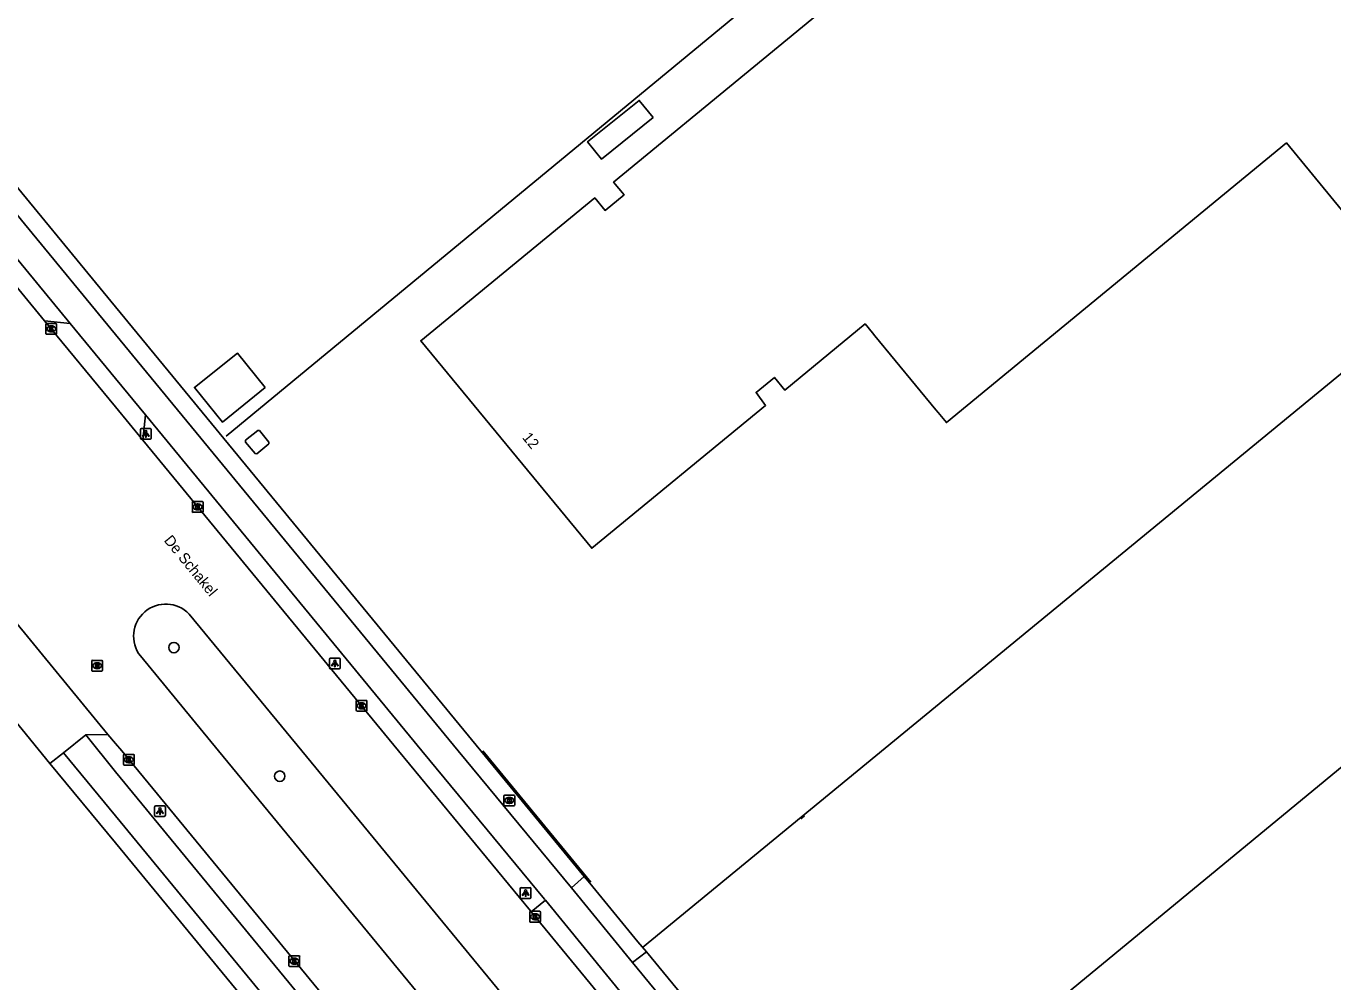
# Model space of a CAD drawing. Extents: x 156141 to 158132, y 385651 to 388399.
# Drawn here: x 156991.7 to 157113.6, y 386478.5 to 386567.6 of the extents above; entities that cross this region are included whole.
import ezdxf

# ---------------------------------------------------------------- set-up
doc = ezdxf.new("R2010")
doc.units = 0
for name, color, linetype in [('IMGEO_Boom', 7, 'Continuous'), ('IMGEO_Brandkraan', 7, 'Continuous'), ('IMGEO_Fietspad_gesloten', 7, 'Continuous'), ('IMGEO_Hek', 7, 'Continuous'), ('IMGEO_Kolk', 7, 'Continuous'), ('IMGEO_Lage_trafo', 7, 'Continuous'), ('IMGEO_Lichtpunt', 7, 'Continuous'), ('IMGEO_Openbare_ruimte_label', 7, 'Continuous'), ('IMGEO_Pand', 7, 'Continuous'), ('IMGEO_Pand_nummerreeks', 7, 'Continuous'), ('IMGEO_Rijbaan_lokaal_gesloten', 7, 'Continuous'), ('IMGEO_Rijbaan_lokaal_open', 7, 'Continuous'), ('IMGEO_Rioolput', 7, 'Continuous'), ('IMGEO_Voetpad_open', 7, 'Continuous')]:
    doc.layers.add(name, color=color, linetype=linetype)

msp = doc.modelspace()

# ---------------------------------------------------------------- linework, layer by layer
at = {"layer": 'IMGEO_Boom'}
for centre in [(157005.46, 386509.64), (157015.33, 386497.65)]:
    msp.add_circle(centre, 0.489, dxfattribs=at)
at = {"layer": 'IMGEO_Brandkraan'}
for p, q in [((157036.25, 386494.96), (157036.25, 386495.81)), ((157036.32, 386495.89), (157037.17, 386495.89)), ((157036.73, 386495.67), (157036.76, 386495.67)), ((157037.25, 386495.81), (157037.25, 386494.96)), ((157037.17, 386494.89), (157036.32, 386494.89)), ((157036.76, 386495.11), (157036.73, 386495.11))]:
    msp.add_line(p, q, dxfattribs=at)
for points in [[(157036.25, 386494.96), (157036.25, 386495.81)], [(157036.32, 386495.89), (157037.17, 386495.89)], [(157036.59, 386495.59), (157036.59, 386495.19), (157036.81, 386495.19)], [(157036.83, 386495.59), (157036.59, 386495.59)], [(157037.25, 386495.81), (157037.25, 386494.96)], [(157037.17, 386494.89), (157036.32, 386494.89)], [(157036.77, 386495.51), (157036.72, 386495.51), (157036.72, 386495.43)], [(157036.72, 386495.43), (157036.77, 386495.43)], [(157036.78, 386495.35), (157036.72, 386495.35), (157036.72, 386495.27)], [(157036.72, 386495.27), (157036.78, 386495.27)]]:
    msp.add_lwpolyline(points, dxfattribs=at)
for centre, radius, start, end in [((157036.32, 386495.81), 0.0765, 91.552, 178.448), ((157036.32, 386495.81), 0.0765, 91.552, 178.448), ((157036.83, 386495.44), 0.145, 59.4692, 91.5367), ((157036.85, 386495.49), 0.0922, 285.5137, 58.1501), ((157037.17, 386495.81), 0.0765, 1.552, 88.448), ((157037.17, 386495.81), 0.0765, 1.552, 88.448), ((157036.32, 386494.96), 0.0765, 181.552, 268.448), ((157036.32, 386494.96), 0.0765, 181.552, 268.448), ((157036.77, 386495.47), 0.0379, 267.8285, 90.9355), ((157036.78, 386495.31), 0.0404, 269.8759, 90.5077), ((157036.81, 386495.44), 0.251, 268.6676, 293.5347), ((157036.86, 386495.3), 0.105, 301.3115, 78.989), ((157037.17, 386494.96), 0.0765, 271.552, 358.448), ((157037.17, 386494.96), 0.0765, 271.552, 358.448)]:
    msp.add_arc(centre, radius, start, end, dxfattribs=at)
for centre, major_axis, ratio, start_param, end_param in [((157036.73, 386495.39), (-0.387, 0.002), 0.722429, 4.712389, 7.853982), ((157036.76, 386495.39), (-0.39, 0.002), 0.717154, 1.570796, 4.712389)]:
    msp.add_ellipse(centre, major_axis=major_axis, ratio=ratio, start_param=start_param, end_param=end_param, dxfattribs=at)
at = {"layer": 'IMGEO_Fietspad_gesloten'}
for points in [[(157042.54, 386487.23), (157031.99, 386500), (157000, 386538.85), (156991.51, 386549.16), (156987.15, 386554.49)], [(156995.78, 386539.85), (156987.04, 386550.47), (156985.5, 386552.36)], [(157002.8, 386531.34), (157028.6, 386500), (157040.04, 386486.18), (157040.11, 386486.1)], [(156997.23, 386501.52), (157000, 386498.06), (157086.19, 386393.38)], [(157084.09, 386391.8), (157000, 386493.95), (156995.15, 386499.84)], [(157048.25, 386480.29), (157042.54, 386487.23)], [(157106.12, 386409.97), (157048.25, 386480.29)]]:
    msp.add_lwpolyline(points, dxfattribs=at)
at = {"layer": 'IMGEO_Hek'}
for points in [[(157112.51, 386613.65), (157010.32, 386529.35)], [(157151.72, 386565.87), (157049.18, 386481.68)], [(157044.35, 386487.76), (157034.27, 386500)], [(157064.27, 386493.95), (157063.94, 386493.68)]]:
    msp.add_lwpolyline(points, dxfattribs=at)
at = {"layer": 'IMGEO_Kolk'}
for p, q in [((156993.52, 386538.93), (156993.52, 386539.78)), ((156993.59, 386539.86), (156994.45, 386539.86)), ((156994.01, 386539.64), (156994.03, 386539.64)), ((156994.52, 386539.78), (156994.52, 386538.93)), ((156994.45, 386538.86), (156993.59, 386538.86)), ((156994.03, 386539.08), (156994, 386539.08)), ((157007.18, 386522.33), (157007.18, 386523.19)), ((157007.25, 386523.26), (157008.1, 386523.26)), ((157007.69, 386522.48), (157007.66, 386522.48)), ((157007.67, 386523.04), (157007.69, 386523.04)), ((157008.18, 386523.19), (157008.18, 386522.33)), ((157008.1, 386522.26), (157007.25, 386522.26)), ((157022.47, 386503.79), (157022.47, 386504.64)), ((157022.54, 386504.71), (157023.39, 386504.71)), ((157022.95, 386504.49), (157022.98, 386504.49)), ((157023.47, 386504.64), (157023.47, 386503.79)), ((157023.39, 386503.71), (157022.54, 386503.71)), ((157022.98, 386503.93), (157022.95, 386503.93)), ((157000.76, 386498.75), (157000.76, 386499.61)), ((157000.83, 386499.68), (157001.69, 386499.68)), ((157001.25, 386499.46), (157001.27, 386499.46)), ((157001.76, 386499.61), (157001.76, 386498.75)), ((157001.69, 386498.68), (157000.83, 386498.68)), ((157001.27, 386498.9), (157001.25, 386498.9)), ((157038.65, 386484.12), (157038.65, 386484.97)), ((157038.73, 386485.05), (157039.58, 386485.05)), ((157039.14, 386484.82), (157039.17, 386484.82)), ((157039.66, 386484.97), (157039.66, 386484.12)), ((157039.58, 386484.04), (157038.73, 386484.04)), ((157039.16, 386484.27), (157039.14, 386484.27)), ((157016.27, 386480.9), (157017.12, 386480.9)), ((157016.19, 386479.97), (157016.19, 386480.83)), ((157017.12, 386479.9), (157016.27, 386479.9)), ((157016.68, 386480.68), (157016.71, 386480.68)), ((157016.7, 386480.12), (157016.68, 386480.12)), ((157017.19, 386480.83), (157017.19, 386479.97))]:
    msp.add_line(p, q, dxfattribs=at)
for points in [[(156993.52, 386538.93), (156993.52, 386539.78)], [(156993.59, 386539.86), (156994.45, 386539.86)], [(156993.84, 386539.56), (156993.96, 386539.56), (156993.96, 386539.41), (156994.09, 386539.56), (156994.26, 386539.56), (156994.11, 386539.41), (156994.26, 386539.16), (156994.11, 386539.16), (156994.03, 386539.32), (156993.96, 386539.25), (156993.96, 386539.16), (156993.84, 386539.16), (156993.84, 386539.56)], [(156994.52, 386539.78), (156994.52, 386538.93)], [(156994.45, 386538.86), (156993.59, 386538.86)], [(157007.18, 386522.33), (157007.18, 386523.19)], [(157007.25, 386523.26), (157008.1, 386523.26)], [(157007.5, 386522.96), (157007.62, 386522.96), (157007.62, 386522.81), (157007.75, 386522.96), (157007.92, 386522.96), (157007.77, 386522.81), (157007.92, 386522.56), (157007.77, 386522.56), (157007.69, 386522.72), (157007.62, 386522.66), (157007.62, 386522.56), (157007.5, 386522.56), (157007.5, 386522.96)], [(157008.18, 386523.19), (157008.18, 386522.33)], [(157008.1, 386522.26), (157007.25, 386522.26)], [(157022.47, 386503.79), (157022.47, 386504.64)], [(157022.54, 386504.71), (157023.39, 386504.71)], [(157022.79, 386504.41), (157022.91, 386504.41), (157022.91, 386504.26), (157023.04, 386504.41), (157023.2, 386504.41), (157023.06, 386504.26), (157023.21, 386504.01), (157023.06, 386504.01), (157022.97, 386504.18), (157022.91, 386504.11), (157022.91, 386504.01), (157022.79, 386504.01), (157022.79, 386504.41)], [(157023.47, 386504.64), (157023.47, 386503.79)], [(157023.39, 386503.71), (157022.54, 386503.71)], [(157000.76, 386498.75), (157000.76, 386499.61)], [(157000.83, 386499.68), (157001.69, 386499.68)], [(157001.08, 386499.38), (157001.2, 386499.38), (157001.2, 386499.23), (157001.33, 386499.38), (157001.5, 386499.38), (157001.35, 386499.23), (157001.5, 386498.98), (157001.35, 386498.98), (157001.27, 386499.15), (157001.2, 386499.08), (157001.2, 386498.98), (157001.08, 386498.98), (157001.08, 386499.38)], [(157001.76, 386499.61), (157001.76, 386498.75)], [(157001.69, 386498.68), (157000.83, 386498.68)], [(157038.65, 386484.12), (157038.65, 386484.97)], [(157038.73, 386485.05), (157039.58, 386485.05)], [(157038.97, 386484.74), (157039.1, 386484.74), (157039.1, 386484.59), (157039.23, 386484.74), (157039.39, 386484.74), (157039.25, 386484.59), (157039.4, 386484.34), (157039.25, 386484.34), (157039.16, 386484.51), (157039.1, 386484.44), (157039.1, 386484.34), (157038.97, 386484.34), (157038.97, 386484.74)], [(157039.66, 386484.97), (157039.66, 386484.12)], [(157039.58, 386484.04), (157038.73, 386484.04)], [(157016.27, 386480.9), (157017.12, 386480.9)], [(157016.19, 386479.97), (157016.19, 386480.83)], [(157017.12, 386479.9), (157016.27, 386479.9)], [(157016.51, 386480.6), (157016.64, 386480.6), (157016.64, 386480.45), (157016.77, 386480.6), (157016.93, 386480.6), (157016.78, 386480.45), (157016.94, 386480.2), (157016.78, 386480.2), (157016.7, 386480.37), (157016.64, 386480.3), (157016.64, 386480.2), (157016.51, 386480.2), (157016.51, 386480.6)], [(157017.19, 386480.83), (157017.19, 386479.97)]]:
    msp.add_lwpolyline(points, dxfattribs=at)
for centre, start, end in [((156993.6, 386539.78), 91.552, 178.448), ((156993.6, 386539.78), 91.552, 178.448), ((156994.44, 386539.78), 1.552, 88.448), ((156994.44, 386539.78), 1.552, 88.448), ((156993.6, 386538.93), 181.552, 268.448), ((156993.6, 386538.93), 181.552, 268.448), ((156994.44, 386538.93), 271.552, 358.448), ((156994.44, 386538.93), 271.552, 358.448), ((157007.25, 386523.18), 91.552, 178.448), ((157007.25, 386523.18), 91.552, 178.448), ((157008.1, 386523.18), 1.552, 88.448), ((157008.1, 386523.18), 1.552, 88.448), ((157007.25, 386522.33), 181.552, 268.448), ((157007.25, 386522.33), 181.552, 268.448), ((157008.1, 386522.33), 271.552, 358.448), ((157008.1, 386522.33), 271.552, 358.448), ((157022.54, 386504.64), 91.552, 178.448), ((157022.54, 386504.64), 91.552, 178.448), ((157023.39, 386504.64), 1.552, 88.448), ((157023.39, 386504.64), 1.552, 88.448), ((157022.54, 386503.79), 181.552, 268.448), ((157022.54, 386503.79), 181.552, 268.448), ((157023.39, 386503.79), 271.552, 358.448), ((157023.39, 386503.79), 271.552, 358.448), ((157000.84, 386499.61), 91.552, 178.448), ((157000.84, 386499.61), 91.552, 178.448), ((157001.68, 386499.61), 1.552, 88.448), ((157001.68, 386499.61), 1.552, 88.448), ((157000.84, 386498.76), 181.552, 268.448), ((157000.84, 386498.76), 181.552, 268.448), ((157001.68, 386498.76), 271.552, 358.448), ((157001.68, 386498.76), 271.552, 358.448), ((157038.73, 386484.97), 91.552, 178.448), ((157038.73, 386484.97), 91.552, 178.448), ((157039.58, 386484.97), 1.552, 88.448), ((157039.58, 386484.97), 1.552, 88.448), ((157038.73, 386484.12), 181.552, 268.448), ((157038.73, 386484.12), 181.552, 268.448), ((157039.58, 386484.12), 271.552, 358.448), ((157039.58, 386484.12), 271.552, 358.448), ((157016.27, 386480.83), 91.552, 178.448), ((157016.27, 386480.83), 91.552, 178.448), ((157017.12, 386480.83), 1.552, 88.448), ((157017.12, 386480.83), 1.552, 88.448), ((157016.27, 386479.98), 181.552, 268.448), ((157016.27, 386479.98), 181.552, 268.448), ((157017.12, 386479.98), 271.552, 358.448), ((157017.12, 386479.98), 271.552, 358.448)]:
    msp.add_arc(centre, 0.0765, start, end, dxfattribs=at)
for centre, major_axis, ratio, start_param, end_param in [((156994.01, 386539.36), (-0.387, 0.002), 0.722429, 4.712389, 7.853982), ((156994.03, 386539.36), (-0.39, 0.002), 0.717154, 1.570796, 4.712389), ((157007.66, 386522.76), (-0.387, 0.002), 0.722429, 4.712389, 7.853982), ((157007.69, 386522.76), (-0.39, 0.002), 0.717154, 1.570796, 4.712389), ((157022.95, 386504.21), (-0.387, 0.002), 0.722429, 4.712389, 7.853982), ((157022.98, 386504.21), (-0.39, 0.002), 0.717154, 1.570796, 4.712389), ((157001.25, 386499.18), (-0.387, 0.002), 0.722429, 4.712389, 7.853982), ((157001.27, 386499.18), (-0.39, 0.002), 0.717154, 1.570796, 4.712389), ((157039.14, 386484.54), (-0.387, 0.002), 0.722429, 4.712389, 7.853982), ((157039.17, 386484.54), (-0.39, 0.002), 0.717154, 1.570796, 4.712389), ((157016.68, 386480.4), (-0.387, 0.002), 0.722429, 4.712389, 7.853982), ((157016.7, 386480.4), (-0.39, 0.002), 0.717154, 1.570796, 4.712389)]:
    msp.add_ellipse(centre, major_axis=major_axis, ratio=ratio, start_param=start_param, end_param=end_param, dxfattribs=at)
at = {"layer": 'IMGEO_Lage_trafo'}
msp.add_lwpolyline([(157014.33, 386528.64), (157013.19, 386527.71), (157013.03, 386527.73), (157012.14, 386528.8), (157012.14, 386528.98), (157013.28, 386529.9), (157013.43, 386529.89), (157014.32, 386528.8), (157014.33, 386528.64)], dxfattribs=at)
at = {"layer": 'IMGEO_Lichtpunt'}
for p, q in [((157002.34, 386529.97), (157002.34, 386529.16)), ((157002.34, 386529.97), (157002.34, 386529.16)), ((157003.24, 386530.06), (157002.43, 386530.06)), ((157003.24, 386530.06), (157002.43, 386530.06)), ((157003.34, 386529.16), (157003.34, 386529.97)), ((157003.34, 386529.16), (157003.34, 386529.97)), ((157002.43, 386529.07), (157003.24, 386529.07)), ((157002.43, 386529.07), (157003.24, 386529.07)), ((157019.98, 386508.56), (157019.98, 386507.75)), ((157019.98, 386508.56), (157019.98, 386507.75)), ((157020.88, 386508.65), (157020.07, 386508.65)), ((157020.88, 386508.65), (157020.07, 386508.65)), ((157020.98, 386507.75), (157020.98, 386508.56)), ((157020.98, 386507.75), (157020.98, 386508.56)), ((157020.07, 386507.66), (157020.88, 386507.66)), ((157020.07, 386507.66), (157020.88, 386507.66)), ((157003.66, 386494.8), (157003.66, 386493.99)), ((157003.66, 386494.8), (157003.66, 386493.99)), ((157004.56, 386494.89), (157003.76, 386494.89)), ((157004.56, 386494.89), (157003.76, 386494.89)), ((157004.66, 386493.99), (157004.66, 386494.8)), ((157004.66, 386493.99), (157004.66, 386494.8)), ((157003.76, 386493.9), (157004.56, 386493.9)), ((157003.76, 386493.9), (157004.56, 386493.9)), ((157037.77, 386487.16), (157037.77, 386486.35)), ((157037.77, 386487.16), (157037.77, 386486.35)), ((157038.67, 386487.25), (157037.87, 386487.25)), ((157038.67, 386487.25), (157037.87, 386487.25)), ((157038.77, 386486.35), (157038.77, 386487.16)), ((157038.77, 386486.35), (157038.77, 386487.16)), ((157037.87, 386486.25), (157038.67, 386486.25)), ((157037.87, 386486.25), (157038.67, 386486.25))]:
    msp.add_line(p, q, dxfattribs=at)
for points in [[(157002.71, 386529.63), (157002.75, 386529.6), (157002.57, 386529.34), (157002.53, 386529.37), (157002.71, 386529.63)], [(157002.82, 386529.58), (157002.86, 386529.58), (157002.86, 386529.26), (157002.82, 386529.26), (157002.82, 386529.58)], [(157002.93, 386529.6), (157002.96, 386529.63), (157003.15, 386529.37), (157003.11, 386529.34), (157002.93, 386529.6)], [(157020.35, 386508.22), (157020.39, 386508.19), (157020.2, 386507.93), (157020.17, 386507.96), (157020.35, 386508.22)], [(157020.45, 386508.17), (157020.5, 386508.17), (157020.5, 386507.85), (157020.45, 386507.85), (157020.45, 386508.17)], [(157020.56, 386508.19), (157020.6, 386508.22), (157020.79, 386507.96), (157020.75, 386507.93), (157020.56, 386508.19)], [(157004.04, 386494.46), (157004.07, 386494.43), (157003.89, 386494.17), (157003.85, 386494.2), (157004.04, 386494.46)], [(157004.14, 386494.41), (157004.18, 386494.41), (157004.18, 386494.09), (157004.14, 386494.09), (157004.14, 386494.41)], [(157004.25, 386494.43), (157004.29, 386494.46), (157004.47, 386494.2), (157004.43, 386494.17), (157004.25, 386494.43)], [(157038.15, 386486.82), (157038.18, 386486.79), (157038, 386486.53), (157037.96, 386486.56), (157038.15, 386486.82)], [(157038.25, 386486.77), (157038.29, 386486.77), (157038.29, 386486.45), (157038.25, 386486.45), (157038.25, 386486.77)], [(157038.36, 386486.79), (157038.4, 386486.82), (157038.58, 386486.56), (157038.54, 386486.53), (157038.36, 386486.79)]]:
    msp.add_lwpolyline(points, dxfattribs=at)
for centre in [(157002.84, 386529.77), (157020.48, 386508.36), (157004.16, 386494.6), (157038.27, 386486.95)]:
    msp.add_circle(centre, 0.0994, dxfattribs=at)
for centre, start, end in [((157002.43, 386529.97), 90, 180), ((157002.43, 386529.97), 90, 180), ((157003.24, 386529.97), 0, 90), ((157003.24, 386529.97), 0, 90), ((157002.43, 386529.16), 180, 270), ((157002.43, 386529.16), 180, 270), ((157003.24, 386529.16), 270, 0), ((157003.24, 386529.16), 270, 360), ((157020.07, 386508.56), 90, 180), ((157020.07, 386508.56), 90, 180), ((157020.07, 386507.75), 180, 270), ((157020.07, 386507.75), 180, 270), ((157020.88, 386508.56), 0, 90), ((157020.88, 386508.56), 0, 90), ((157020.88, 386507.75), 270, 0), ((157020.88, 386507.75), 270, 360), ((157003.76, 386494.8), 90, 180), ((157003.76, 386494.8), 90, 180), ((157004.56, 386494.8), 0, 90), ((157004.56, 386494.8), 0, 90), ((157003.76, 386493.99), 180, 270), ((157003.76, 386493.99), 180, 270), ((157004.56, 386493.99), 270, 0), ((157004.56, 386493.99), 270, 360), ((157037.87, 386487.16), 90, 180), ((157037.87, 386487.16), 90, 180), ((157038.67, 386487.16), 0, 90), ((157038.67, 386487.16), 0, 90), ((157037.87, 386486.35), 180, 270), ((157037.87, 386486.35), 180, 270), ((157038.67, 386486.35), 270, 0), ((157038.67, 386486.35), 270, 360)]:
    msp.add_arc(centre, 0.0946, start, end, dxfattribs=at)
at = {"layer": 'IMGEO_Pand'}
for points in [[(157135.47, 386578.26), (157123.98, 386568.81), (157130.53, 386560.85), (157115.81, 386548.73), (157109.24, 386556.7), (157077.52, 386530.62), (157076.75, 386531.56), (157076.55, 386531.8), (157070.84, 386538.71), (157070.64, 386538.98), (157069.93, 386539.82), (157062.44, 386533.65), (157061.47, 386534.83), (157059.76, 386533.43), (157060.65, 386532.22), (157044.43, 386518.9), (157028.49, 386538.25), (157044.71, 386551.57), (157045.68, 386550.4), (157047.45, 386551.87), (157046.48, 386553.04), (157111.92, 386606.86), (157132.44, 386581.94)], [(157050.16, 386559.06), (157045.34, 386555.2), (157044.05, 386556.81), (157048.87, 386560.67), (157050.16, 386559.06)], [(157116.21, 386500), (157127.1, 386508.96), (157133.36, 386514.12), (157165.78, 386540.8), (157199.38, 386500), (157212.51, 386484.05), (157183.01, 386459.8), (157181.86, 386461.2), (157166.86, 386448.84), (157138.86, 386425.77), (157126.75, 386415.79), (157110.04, 386436.12), (157108.67, 386434.94), (157079.79, 386470.01), (157116.21, 386500)], [(157013.98, 386533.89), (157009.98, 386530.67), (157007.38, 386533.9), (157011.38, 386537.11), (157013.98, 386533.89)]]:
    msp.add_lwpolyline(points, dxfattribs=at)
at = {"layer": 'IMGEO_Rijbaan_lokaal_gesloten'}
for points in [[(156984.32, 386551.23), (156989.45, 386544.94), (156993.4, 386540.12)], [(156993.4, 386540.12), (157000, 386532.08), (157002.55, 386528.98)], [(157002.55, 386528.98), (157026.41, 386500), (157038.73, 386485.08), (157038.8, 386485)], [(156999.31, 386501.55), (156993.21, 386508.96), (156985.57, 386518.24), (156981.89, 386522.72)], [(157109.73, 386387.85), (157107.76, 386390.26), (157017.39, 386500), (157006.88, 386512.77)], [(157002.33, 386508.86), (157009.63, 386500), (157103.14, 386386.43), (157105.1, 386384.05)], [(157099.71, 386379.64), (157000.59, 386500), (157000, 386500.71), (156999.31, 386501.55)], [(157046.39, 386475.77), (157046.31, 386475.87), (157038.8, 386485)]]:
    msp.add_lwpolyline(points, dxfattribs=at)
msp.add_arc((157004.7, 386510.7), 3, 43.6011, 217.7923, dxfattribs=at)
at = {"layer": 'IMGEO_Rijbaan_lokaal_open'}
for points in [[(156993.4, 386540.12), (156995.78, 386539.85)], [(157002.8, 386531.34), (157000, 386534.73), (156995.78, 386539.85)], [(157002.55, 386528.98), (157002.8, 386531.34)], [(156986.18, 386508.22), (156987.59, 386506.51), (156993.9, 386498.84)], [(156995.15, 386499.84), (156997.23, 386501.52)], [(156997.23, 386501.52), (156999.31, 386501.55)], [(156993.9, 386498.84), (156995.15, 386499.84)], [(157038.8, 386485), (157040.11, 386486.1)], [(157040.11, 386486.1), (157047.63, 386476.93), (157047.71, 386476.84)]]:
    msp.add_lwpolyline(points, dxfattribs=at)
at = {"layer": 'IMGEO_Rioolput'}
for p, q in [((156997.8, 386507.53), (156997.8, 386508.38)), ((156997.87, 386508.45), (156998.73, 386508.45)), ((156998.29, 386508.23), (156998.31, 386508.23)), ((156998.8, 386508.38), (156998.8, 386507.53)), ((156998.73, 386507.45), (156997.87, 386507.45)), ((156998.31, 386507.67), (156998.28, 386507.67))]:
    msp.add_line(p, q, dxfattribs=at)
for points in [[(156997.8, 386507.53), (156997.8, 386508.38)], [(156997.87, 386508.45), (156998.73, 386508.45)], [(156998.39, 386508.15), (156998.13, 386508.15), (156998.13, 386507.75)], [(156998.13, 386507.75), (156998.26, 386507.75), (156998.26, 386507.91), (156998.27, 386507.91)], [(156998.31, 386508.07), (156998.26, 386508.07), (156998.26, 386507.99)], [(156998.26, 386507.99), (156998.31, 386507.99)], [(156998.32, 386507.88), (156998.39, 386507.75), (156998.53, 386507.75), (156998.46, 386507.88)], [(156998.8, 386508.38), (156998.8, 386507.53)], [(156998.73, 386507.45), (156997.87, 386507.45)]]:
    msp.add_lwpolyline(points, dxfattribs=at)
for centre, radius, start, end in [((156997.87, 386508.38), 0.0765, 91.552, 178.448), ((156997.87, 386508.38), 0.0765, 91.552, 178.448), ((156998.27, 386507.86), 0.0533, 26.0293, 88.6989), ((156998.32, 386507.97), 0.0964, 77.0061, 93.1865), ((156998.3, 386508.18), 0.19, 274.7715, 282.9687), ((156998.33, 386508.03), 0.0378, 276.6634, 79.6772), ((156998.39, 386508.04), 0.109, 350.3612, 89.416), ((156998.38, 386508.04), 0.112, 277.5842, 350.9817), ((156998.37, 386507.82), 0.108, 29.5134, 73.7905), ((156998.72, 386508.38), 0.0765, 1.552, 88.448), ((156998.72, 386508.38), 0.0765, 1.552, 88.448), ((156997.87, 386507.53), 0.0765, 181.552, 268.448), ((156997.87, 386507.53), 0.0765, 181.552, 268.448), ((156998.72, 386507.53), 0.0765, 271.552, 358.448), ((156998.72, 386507.53), 0.0765, 271.552, 358.448)]:
    msp.add_arc(centre, radius, start, end, dxfattribs=at)
for centre, major_axis, ratio, start_param, end_param in [((156998.29, 386507.95), (-0.387, 0.002), 0.722429, 4.712389, 7.853982), ((156998.31, 386507.95), (-0.39, 0.002), 0.717154, 1.570796, 4.712389)]:
    msp.add_ellipse(centre, major_axis=major_axis, ratio=ratio, start_param=start_param, end_param=end_param, dxfattribs=at)
at = {"layer": 'IMGEO_Voetpad_open'}
for points in [[(156988.38, 386555.54), (157000, 386541.41), (157034.1, 386500), (157043.74, 386488.28)], [(156993.9, 386498.84), (157000, 386491.44), (157082.67, 386391)], [(157043.74, 386488.28), (157042.54, 386487.23)], [(157043.74, 386488.28), (157044.25, 386487.67), (157048.74, 386482.21), (157049.53, 386481.28)], [(157049.53, 386481.28), (157048.25, 386480.29)], [(157049.53, 386481.28), (157107.84, 386410.44)]]:
    msp.add_lwpolyline(points, dxfattribs=at)

# ---------------------------------------------------------------- texts
at = {"layer": 'IMGEO_Openbare_ruimte_label'}
msp.add_text('De Schakel', height=1, rotation=309.4829, dxfattribs=at).set_placement((157004.48, 386519.61))
at = {"layer": 'IMGEO_Pand_nummerreeks'}
msp.add_text('12', height=1, rotation=309.4651, dxfattribs=at).set_placement((157037.9, 386529.21))

doc.saveas('drawing.dxf')
